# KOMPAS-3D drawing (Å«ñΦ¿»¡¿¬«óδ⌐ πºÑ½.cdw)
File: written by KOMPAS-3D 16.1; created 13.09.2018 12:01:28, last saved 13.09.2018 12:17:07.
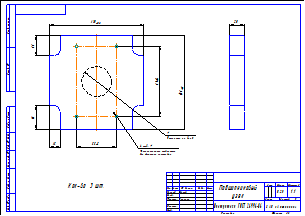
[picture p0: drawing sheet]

Sheet 1: A3, landscape

Title block, sheet 1: name: Подшипниковый / узел; material: Полипропилен  ГОСТ 26996-86; mass: 0,25; scale: 1:1; sheets: 1; organisation: ЗАО «Астерион»; sheet format: A3; drawn by: Милов; technical control: Лучихин

Views: Вид 1, Спереди, Проекционный вид 2
Referenced files in \\192.168.87.28\Konstructor_doc\Мембранные насосы\Мембранный электропривод\А302-00.00.000 - ASTRA-302 (МЭ200)\3Д\Доработка\: Подшипниковый узел.m3d
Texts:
  Уточнить по валу
  Технологические отверстия
  для фиксации заготовки
  Кол-во  3 шт.
Dimensions and other numbers on the sheet: 130; 28; 33; 15; 55±5; 97±5; 4 отв.; 20; 1:1; 1; 0,25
